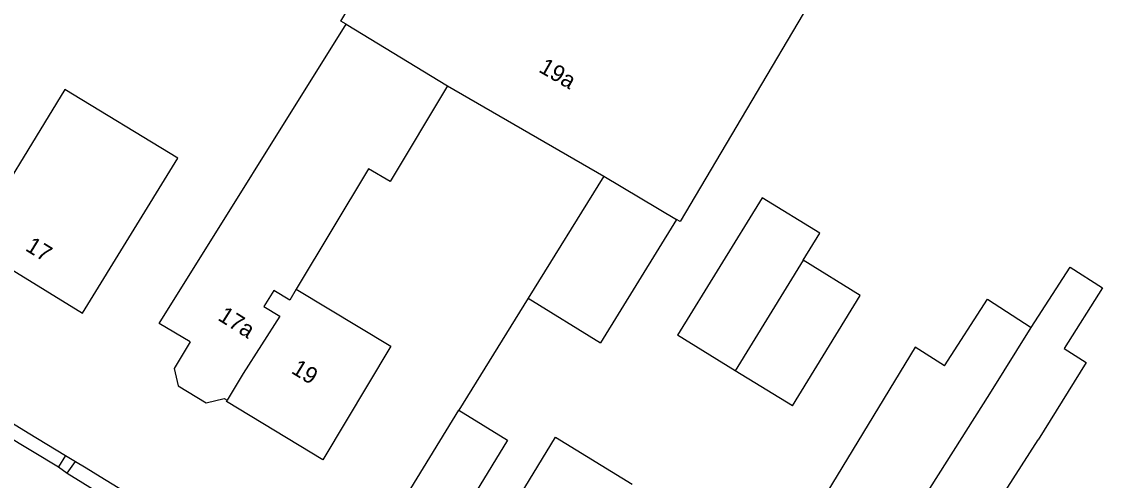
# Model space of a CAD drawing. Extents: x 136000 to 141000, y 400494 to 402006.
# Drawn here: x 137735.7 to 137801.2, y 401916 to 401943.7 of the extents above; entities that cross this region are included whole.
import ezdxf

# ---------------------------------------------------------------- set-up
doc = ezdxf.new("R2010")
doc.units = 0
for name, color, linetype in [('gg-afsc-erfafscheiding', 7, 'Continuous'), ('gg-afsc-muur', 7, 'Continuous'), ('gg-anno-huisnummerreeks BGT', 7, 'Continuous'), ('gg-bbg-bijgebouw', 7, 'Continuous'), ('gg-bbg-gedigitaliseerde bebouwing', 7, 'Continuous'), ('gg-bbg-gedigitaliseerde bijgebouw', 7, 'Continuous'), ('gg-bbg-hoofdgebouw', 7, 'Continuous'), ('gg-bbg-tussenscheiding', 7, 'Continuous'), ('gg-knt-verharding', 7, 'Continuous'), ('gg-knt-verharding nz', 7, 'Continuous')]:
    doc.layers.add(name, color=color, linetype=linetype)

msp = doc.modelspace()

# ---------------------------------------------------------------- linework, layer by layer
at = {"layer": 'gg-afsc-erfafscheiding'}
for p, q in [((137735.122, 401919.416), (137736.065, 401918.844)), ((137736.065, 401918.844), (137738.331, 401917.468)), ((137738.331, 401917.468), (137738.928, 401917.106)), ((137738.928, 401917.106), (137739.569, 401916.717)), ((137739.569, 401916.717), (137740.436, 401916.19)), ((137740.436, 401916.19), (137744.052, 401913.995))]:
    msp.add_line(p, q, dxfattribs=at)
at = {"layer": 'gg-afsc-muur'}
msp.add_line((137766.364, 401926.988), (137762.16, 401920.2), dxfattribs=at)
at = {"layer": 'gg-bbg-bijgebouw'}
for p, q in [((137770.939, 401934.368), (137766.364, 401926.988)), ((137766.364, 401926.988), (137770.738, 401924.283)), ((137778.906, 401922.596), (137775.412, 401924.747)), ((137782.371, 401920.463), (137778.906, 401922.596))]:
    msp.add_line(p, q, dxfattribs=at)
at = {"layer": 'gg-bbg-gedigitaliseerde bebouwing'}
for p, q in [((137790.893, 401957.461), (137775.566, 401931.623)), ((137744, 401925.46), (137755.332, 401943.563)), ((137775.566, 401931.623), (137775.355, 401931.749))]:
    msp.add_line(p, q, dxfattribs=at)
for points in [[(137755.332, 401943.563), (137755.003, 401943.755), (137770.874, 401970.066)], [(137762.16, 401920.2), (137765.112, 401918.387), (137762.266, 401913.73), (137764.299, 401912.488)], [(137764.299, 401912.488), (137768.016, 401918.571), (137772.664, 401915.729)]]:
    msp.add_lwpolyline(points, dxfattribs=at)
at = {"layer": 'gg-bbg-gedigitaliseerde bijgebouw'}
for p, q in [((137775.355, 401931.749), (137770.738, 401924.283)), ((137791.109, 401908.877), (137797.26, 401918.408))]:
    msp.add_line(p, q, dxfattribs=at)
for points in [[(137783.02, 401929.28), (137784.024, 401930.91), (137780.53, 401933.061), (137775.412, 401924.747)], [(137782.371, 401920.463), (137786.486, 401927.147), (137783.02, 401929.28)], [(137796.837, 401925.204), (137799.209, 401928.867), (137801.155, 401927.607), (137798.83, 401923.94), (137800.169, 401923.091), (137797.26, 401918.408)], [(137791.589, 401922.899), (137794.191, 401926.917), (137796.837, 401925.204)], [(137791.589, 401922.899), (137789.805, 401924.01), (137782.866, 401912.605)]]:
    msp.add_lwpolyline(points, dxfattribs=at)
at = {"layer": 'gg-bbg-hoofdgebouw'}
for p, q in [((137761.47, 401939.83), (137770.939, 401934.368)), ((137745.884, 401924.341), (137744, 401925.46))]:
    msp.add_line(p, q, dxfattribs=at)
for points in [[(137732.545, 401930.257), (137739.348, 401926.083), (137745.133, 401935.467), (137738.289, 401939.621), (137732.545, 401930.257)], [(137761.47, 401939.83), (137757.99, 401934.04), (137756.69, 401934.82), (137752.3, 401927.52)], [(137752.3, 401927.52), (137758.04, 401924.08), (137753.91, 401917.2), (137748.08, 401920.74), (137748.123, 401920.811)], [(137745.884, 401924.341), (137744.905, 401922.733), (137745.162, 401921.675), (137746.853, 401920.658), (137747.935, 401920.92), (137748.123, 401920.811)], [(137760.174, 401905.727), (137755.39, 401908.65), (137759.48, 401915.34), (137759.25, 401915.47), (137762.16, 401920.2)]]:
    msp.add_lwpolyline(points, dxfattribs=at)
at = {"layer": 'gg-bbg-tussenscheiding'}
for p, q in [((137755.332, 401943.563), (137761.47, 401939.83)), ((137770.939, 401934.368), (137775.355, 401931.749)), ((137783.02, 401929.28), (137778.906, 401922.596))]:
    msp.add_line(p, q, dxfattribs=at)
for points in [[(137752.3, 401927.52), (137751.92, 401926.868), (137750.95, 401927.44), (137750.334, 401926.478), (137751.305, 401925.896), (137749.1, 401922.43), (137748.123, 401920.811)], [(137787.215, 401909.958), (137794.335, 401921.188), (137796.837, 401925.204)]]:
    msp.add_lwpolyline(points, dxfattribs=at)
at = {"layer": 'gg-knt-verharding'}
for p, q in [((137738.331, 401917.468), (137737.895, 401916.768)), ((137737.895, 401916.768), (137738.419, 401916.394)), ((137738.419, 401916.394), (137738.928, 401917.106))]:
    msp.add_line(p, q, dxfattribs=at)
at = {"layer": 'gg-knt-verharding nz'}
for p, q in [((137734.65, 401918.73), (137737.895, 401916.768)), ((137738.419, 401916.394), (137743.646, 401913.192))]:
    msp.add_line(p, q, dxfattribs=at)

# ---------------------------------------------------------------- texts
at = {"layer": 'gg-anno-huisnummerreeks BGT'}
for s, rotation, p in [('19a', 330.1, (137766.943, 401940.712)), ('17', 328.5, (137735.835, 401929.906)), ('17a', 327.9, (137747.495, 401925.699)), ('19', 328.7, (137751.945, 401922.489))]:
    msp.add_text(s, height=1, rotation=rotation, dxfattribs=at).set_placement(p)

doc.saveas('drawing.dxf')
